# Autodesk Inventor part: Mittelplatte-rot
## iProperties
Created: 2004-10
Part Number: Mittelplatte-rot
Document SubType Name: Modeling
Designer: sahrens
Manufacturer: Standard
Standards Organization: Custom
Author: sahrens
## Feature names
1. Extrusion1
2. Extrusion2
3. Rundung2 [Fillet]
